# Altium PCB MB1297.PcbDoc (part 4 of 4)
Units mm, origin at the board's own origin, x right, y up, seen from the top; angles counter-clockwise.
Board outline 90.1 x 62.11 mm, 4 copper layers (Top Layer, GND, POWER+GND, Bottom Layer), stack 0.778 mm thick; 235 components, 175 nets, 1727 pads, 1 vias.
Unrouted connection lines stored in the file: 1.
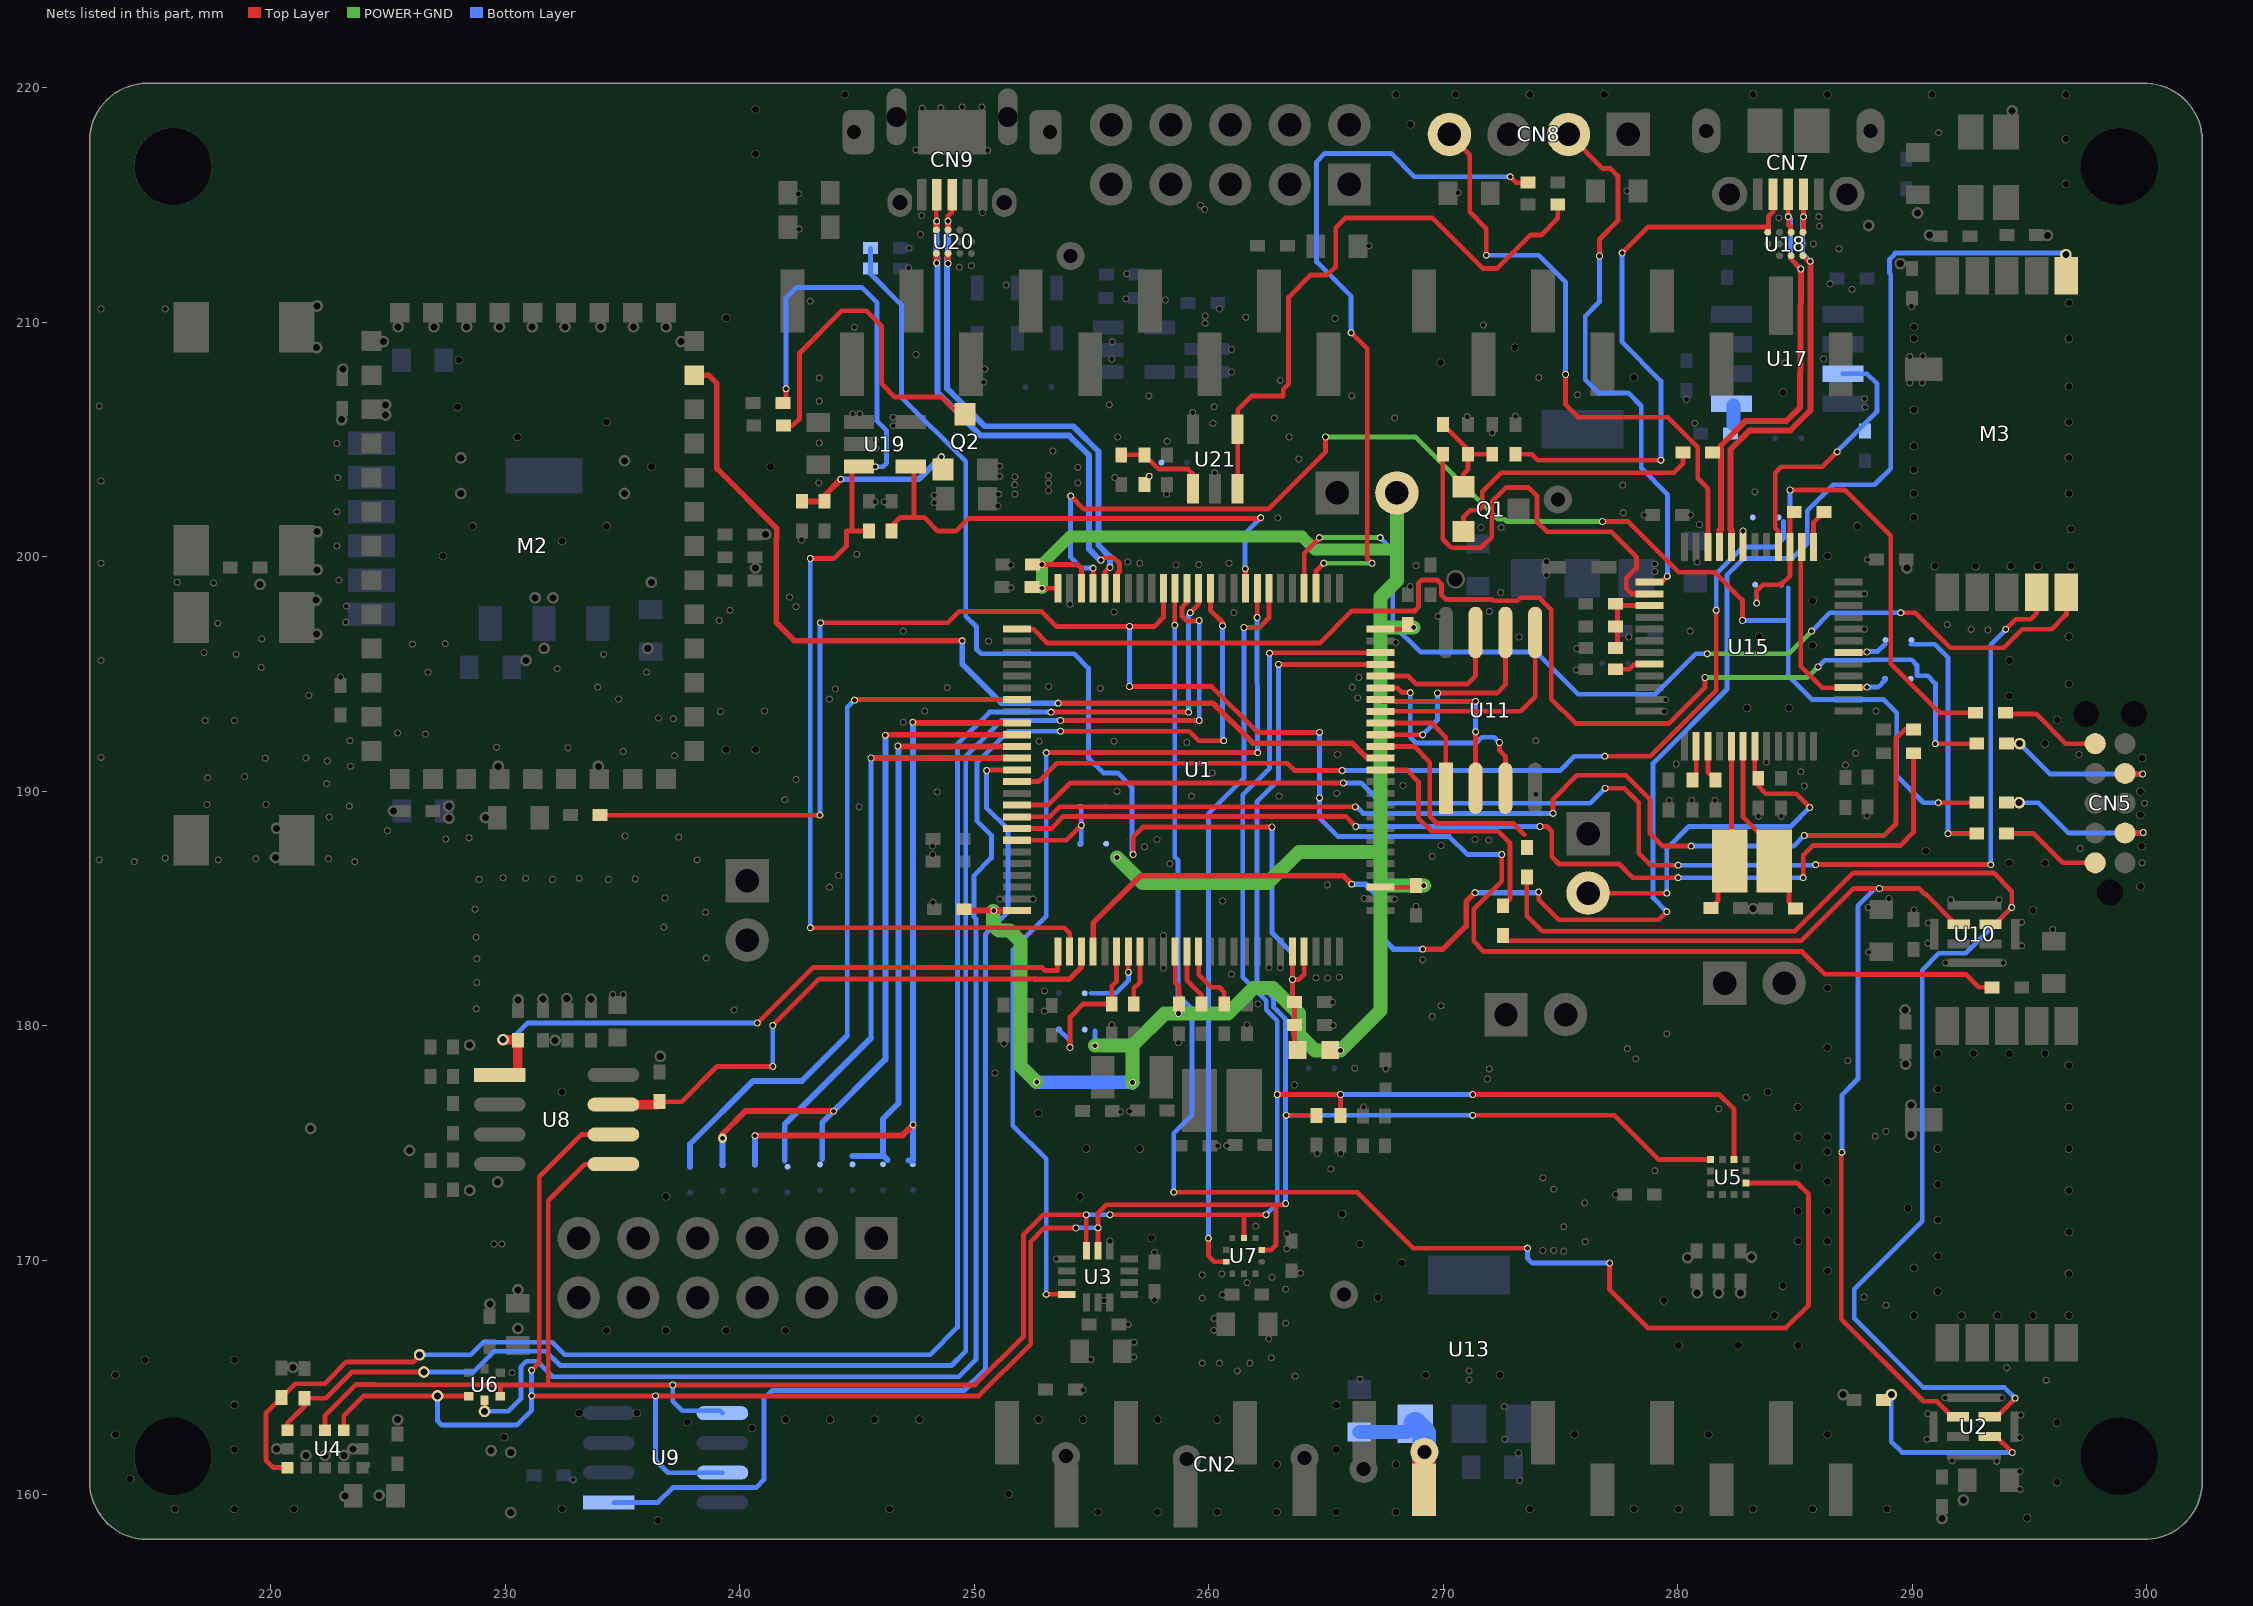
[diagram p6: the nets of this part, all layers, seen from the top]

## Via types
v1: diameter 0.4, hole 0.2, Top Layer to Bottom Layer, tented both sides, 1 vias

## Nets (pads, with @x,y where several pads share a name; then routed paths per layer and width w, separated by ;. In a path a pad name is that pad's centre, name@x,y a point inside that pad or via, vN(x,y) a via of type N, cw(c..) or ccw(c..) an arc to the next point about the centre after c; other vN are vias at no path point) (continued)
NetM2_34: M2.34 pad.33@249.479,196.418 pad.93@253.568,193.751 U1.39 | length 41.1
  Top Layer w0.24: M2.34@238.045,207.742 238.663,207.742 239.014,207.391 239.014,203.759 241.569,201.204 241.569,200.757 241.554,200.742 241.554,197.18 242.316,196.418 pad.33@249.479,196.418 ; pad.93@253.568,193.751 260.172,193.751 261.874,192.049 266.106,192.049 266.749,191.406 U1.39@267.313,191.406
  Bottom Layer w0.24: pad.33@249.479,196.418 249.479,195.422 251.15,193.751 pad.93@253.568,193.751
NetM3_1: M3.1 pad.46@279.527,184.861 pad.47@271.348,185.674 pad.49@274.066,185.699 pad.86@266.09,186.03 pad.91@269.113,183.261 pad.108@296.545,212.877 U1.4 | length 73.4
  Top Layer w0.204: pad.49@274.066,185.699 274.066,185.369 274.916,184.52 279.185,184.52 pad.46@279.527,184.861
  Top Layer w0.24: U1.4@255.063,183.156 255.063,184.374 257.073,186.385 265.735,186.385 pad.86@266.09,186.03 ; pad.91@269.113,183.261 269.977,183.261 270.967,184.252 270.967,185.293 pad.47@271.348,185.674
  Bottom Layer w0.204: pad.46@279.527,184.861 278.943,185.445 278.943,191.186 282.093,194.336 282.093,199.213 282.804,199.923 284.886,199.923 285.521,200.558 285.521,201.955 286.633,203.067 288.385,203.067 289.077,203.759 289.077,212.039 289.03,212.086 289.03,212.684 289.252,212.907 289.252,212.95 296.472,212.95 pad.108@296.545,212.877
  Bottom Layer w0.24: pad.86@266.09,186.03 266.689,186.03 267.185,185.534 267.185,183.944 267.868,183.261 pad.91@269.113,183.261 ; pad.47@271.348,185.674 274.041,185.674 pad.49@274.066,185.699
NetM3_10: M3.10 pad.23@293.98,196.901 pad.28@276.901,190.121 pad.29@280.01,186.842 pad.31@293.345,186.868 pad.32@285.877,186.868 pad.135@265.735,190.348 U1.91 | length 57.9
  Top Layer w0.204: U1.91@251.813,189.406 253.135,189.406 254.076,190.348 pad.135@265.735,190.348 ; pad.28@276.901,190.121 277.722,190.121 278.333,189.509 278.333,187.35 278.841,186.842 pad.29@280.01,186.842 ; pad.32@285.877,186.868 pad.31@293.345,186.868 ; pad.23@293.98,196.901 294.411,197.333 295.046,197.333 295.3,197.587 M3.10@295.3,198.488
  Bottom Layer w0.204: pad.135@265.735,190.348 266.497,190.348 267.36,189.484 276.265,189.484 pad.28@276.901,190.121 ; pad.29@280.01,186.842 pad.32@285.852,186.842 ; pad.31@293.345,186.868 293.345,196.24 293.98,196.875 pad.23@293.98,196.901
NetM3_11: M3.11 pad.50@264.719,200.812 pad.244 pad.245 pad.246 pad.247 U1.54 | length 42.5
  Top Layer w0.204: U1.54@264.063,198.656 264.063,200.156 pad.50@264.719,200.812 ; pad.245@289.509,197.612 290.119,197.612 291.617,196.113 293.903,196.113 294.691,196.901 295.935,196.901 296.57,197.536 M3.11@296.57,198.488
  POWER+GND w0.204: pad.50@264.719,200.812 pad.244@267.31,200.812 ; pad.247@281.254,195.859 284.734,195.859 pad.246@285.699,196.825
  Bottom Layer w0.204: pad.244@267.31,200.812 267.843,200.279 267.843,197.104 269.011,195.936 273.939,195.936 275.742,194.132 279.044,194.132 280.772,195.859 pad.247@281.254,195.859 ; pad.246@285.699,196.825 286.487,197.612 pad.245@289.509,197.612
NetQ1_1: Q1.1 R45.2 R46.2 R48.2 | length 4.2
  Top Layer w0.204: R45.2@269.977,205.638 271.043,204.572 R46.2@271.043,204.368 ; Q1.1@270.852,202.982 270.852,203.517 271.043,203.708 R46.2@271.043,204.368 ; R48.2@272.085,204.368 R46.2@271.043,204.368
NetQ1_2: Q1.2 R50.1 | length 11.8
  Top Layer w0.204: Q1.2@270.852,201.082 270.852,201.688 271.145,201.981 271.501,201.981 271.653,202.133 271.653,202.768 272.466,203.581 279.832,203.581 280.213,203.962 R50.1@280.213,204.445
NetQ2_1: pad.145@244.297,203.302 pad.146@248.59,204.267 Q2.1 R57.2 R59.2 | length 6.9
  Top Layer w0.254: R59.2@242.646,202.362 R57.2@243.606,202.362 243.606,202.611 pad.145@244.297,203.302
  Bottom Layer w0.254: pad.145@244.297,203.302 247.625,203.302 pad.146@248.59,204.267
NetQ2_3: Q2.3 R55.1 | length 14.7
  Top Layer w0.204: R55.1@241.859,205.588 242.24,205.588 242.545,205.892 242.545,208.686 244.348,210.49 245.389,210.49 246.05,209.829 246.05,207.366 246.609,206.807 248.615,206.807 249.352,206.07 Q2.3@249.606,206.07
NetR1_2: pad.32@229.895,179.4 pad.58@240.741,180.111 R1.2 U1.1 U8.1 | length 28.7
  Top Layer w0.204: pad.58@240.741,180.111 243.103,182.474 252.882,182.474 253.009,182.347 253.543,182.347 253.543,183.137 U1.1@253.563,183.156
  Top Layer w0.4: U8.1@229.756,177.902 230.556,177.902 230.53,177.927 R1.2@230.53,179.375 230.505,179.4 pad.32@229.895,179.4
  Bottom Layer w0.204: 230.226,179.4 230.937,180.111 pad.58@240.741,180.111
  Bottom Layer w0.24: pad.32@229.895,179.4 230.226,179.4
NetR4_2: pad.59@241.402,180.01 pad.60@241.402,178.257 R4.2 U1.3 U8.7 | length 24.1
  Top Layer w0.204: R4.2@236.576,176.759 237.515,176.759 239.014,178.257 pad.60@241.402,178.257 ; pad.59@241.402,180.01 243.383,181.991 252.576,181.991
  Top Layer w0.24: 252.576,181.991 252.594,181.974 254.033,181.974 254.563,182.503 U1.3@254.563,183.156
  Top Layer w0.4: U8.7@234.606,176.632 236.449,176.632 R4.2@236.576,176.759
  Bottom Layer w0.204: pad.60@241.402,178.257 pad.59@241.402,180.01
NetR5_1: R5.1 U1.12 | length 2.5
  Top Layer w0.204: U1.12@259.063,183.156 259.063,181.932 259.69,181.305 R5.1@259.69,180.924
NetR6_1: pad.165 pad.166 R6.1 U2.3 U10.3 | length 56.5
  Top Layer w0.2: R6.1@273.558,186.334 273.558,184.683 274.218,184.023 284.988,184.023 287.477,186.512 293.472,186.512 294.157,185.826 294.157,185.801 294.234,185.725 pad.166@294.234,185.039 293.526,184.331 U10.3@293.334,184.331 ; U2.3@293.3,163.327 293.604,163.327 pad.165@294.386,164.109
  Bottom Layer w0.2: pad.166@294.234,185.039 292.278,183.083 291.135,183.083 290.424,182.372 290.424,171.653 287.528,168.758 287.528,167.513 290.474,164.567 293.929,164.567 pad.165@294.386,164.109
NetR6_2: R6.2 U1.40 | length 9.1
  Top Layer w0.204: U1.40@267.313,191.906 268.748,191.906 269.418,191.237 269.418,188.925 269.723,188.62 272.974,188.62 273.456,188.138
NetR7_1: R7.1 U1.13 | length 2.9
  Top Layer w0.204: U1.13@259.563,183.156 259.563,182.169 260.096,181.635 260.452,181.635 260.655,181.432 R7.1@260.655,180.924
NetR10_2: pad.3@236.398,164.211 pad.9@262.966,195.406 pad.11@263.271,172.415 pad.14@227.101,164.211 pad.15@231.115,164.211 pad.16@231.115,165.303 pad.17@255.27,171.378 pad.18@254.33,171.374 pad.20@263.296,176.174 pad.151 R10.2 U1.47 U3.13 U4.10 U5.1 U6.2 U7.2 U8.6 U9.7 | length 121.5
  Top Layer w0.204: U4.10@223.101,162.75 223.101,163.36 223.952,164.211 pad.14@227.101,164.211 228.416,164.211 U6.2@228.433,164.194 ; pad.15@231.115,164.211 pad.3@236.398,164.211 250.19,164.211 252.401,166.422 252.401,170.791 252.984,171.374 pad.18@254.33,171.374 ; pad.16@231.115,165.303 231.445,165.633 231.445,173.558 233.248,175.362 U8.6@234.606,175.362 ; U3.13@255.27,170.391 pad.17@255.27,171.378 255.27,172.009 255.626,172.364 262.763,172.364 ; U7.2@262.256,170.43 262.632,170.43 262.865,170.663 262.865,172.364 pad.11@263.22,172.364 ; pad.9@262.966,195.406 U1.47@267.313,195.406 ; pad.20@263.296,176.174 R10.2@264.592,176.174 ; pad.151@271.247,176.174 277.292,176.174 279.171,174.295 U5.1@281.397,174.295
  Bottom Layer w0.204: pad.14@227.101,164.211 227.101,163.144 227.279,162.966 230.48,162.966 231.115,163.601 pad.15@231.115,164.211 pad.16@231.115,165.303 ; pad.3@236.398,164.211 236.398,161.468 236.931,160.934 U9.7@239.255,160.934 ; pad.18@254.334,171.378 pad.17@255.27,171.378 ; pad.9@262.966,195.406 262.966,190.475 262.052,189.56 262.052,181.896 262.75,181.198 262.75,180.808 263.22,180.338 263.22,180.309 263.268,180.261 pad.11@263.268,172.418 ; pad.20@263.395,176.174 pad.151@271.247,176.174
NetR11_2: pad.2@237.134,164.677 pad.8@262.585,195.885 pad.12@262.433,171.933 pad.13@255.778,171.933 pad.14@254.77,171.933 pad.19@262.914,177.063 pad.152@271.247,177.063 pad.153@265.608,177.063 R11.2 U1.48 U3.14 U4.9 U5.11 U6.4 U7.4 U8.5 U9.5 | length 117
  Top Layer w0.204: U4.9@222.301,162.75 222.301,163.373 223.622,164.694 224.409,164.694 224.415,164.688 229.794,164.688 229.783,164.677 ; U6.4@229.783,164.194 229.783,164.677 ; U8.5@234.606,174.092 233.375,174.092 231.826,172.542 231.826,164.677 ; U3.14@254.77,170.391 pad.14@254.77,171.933 252.933,171.933 252.095,171.094 252.095,166.751 250.021,164.677 pad.2@237.134,164.677 231.826,164.677 ; pad.13@255.778,171.933 261.493,171.933 ; U7.4@261.493,170.943 261.493,171.933 ; pad.12@262.433,171.933 261.493,171.933 ; pad.8@262.585,195.885 262.607,195.906 U1.48@267.313,195.906 ; pad.19@262.914,177.063 pad.153@265.608,177.063 R11.2@265.608,176.174 ; pad.152@271.247,177.063 281.762,177.063 282.397,176.428 U5.11@282.397,174.295 ; 229.783,164.677 231.826,164.677
  Bottom Layer w0.204: pad.2@237.134,164.677 237.134,163.975 237.535,163.574 239.155,163.574 U9.5@239.255,163.474 ; pad.14@254.77,171.933 pad.13@255.778,171.933 ; pad.12@262.433,171.933 262.914,172.414 262.914,180.212 262.444,180.682 262.444,181.071 261.442,182.073 261.442,189.84 262.585,190.983 pad.8@262.585,195.885 ; pad.153@265.608,177.063 pad.152@271.247,177.063
NetR12_1: R12.1 U1.8 | length 2.3
  Top Layer w0.204: R12.1@256.794,180.924 256.794,181.585 257.063,181.853 U1.8@257.063,183.156
NetR13_1: pad.167 pad.168 R13.1 U2.4 U10.4 | length 46.9
  Top Layer w0.2: 290.271,185.852 290.525,185.598 290.582,185.598 291.848,184.331 U10.4@291.984,184.331
  Top Layer w0.204: R13.1@272.542,183.845 272.771,183.617 285.267,183.617 287.503,185.852 pad.168@288.595,185.852 290.271,185.852 ; pad.167@286.995,174.6 286.969,174.574 286.969,167.488 290.474,163.982 291.041,163.982 291.696,163.327 U2.4@291.95,163.327
  Bottom Layer w0.204: pad.167@286.995,174.6 286.995,177.038 287.68,177.724 287.68,185.108 288.424,185.852 pad.168@288.595,185.852
NetR13_2: R13.2 U1.38 | length 10.5
  Top Layer w0.204: U1.38@267.313,190.906 268.427,190.906 268.935,190.398 268.935,188.849 269.494,188.29 272.339,188.29 272.845,187.784 272.845,185.418 R13.2@272.542,185.115
NetR14_2: pad.17@226.517,165.227 pad.25@259.588,197.282 pad.28@253.67,193.015 pad.29@259.588,193.015 R14.2 U1.64 U4.7 | length 73.5
  Top Layer w0.204: U4.7@220.701,162.75 220.701,163.043 221.437,163.779 R14.2@221.437,164.109 222.326,164.109 223.444,165.227 pad.17@226.517,165.227 ; pad.28@253.67,193.015 pad.29@259.588,193.015 ; U1.64@259.063,198.656 259.063,198.052 258.853,197.842 258.853,197.465 259.06,197.258 259.564,197.258 pad.25@259.588,197.282
  Bottom Layer w0.204: pad.17@226.517,165.227 228.625,165.227 229.514,166.116 231.724,166.116 232.334,165.506 249.022,165.506 249.633,166.118 249.633,191.492 251.155,193.015 pad.28@253.67,193.015 ; pad.29@259.588,193.015 pad.25@259.588,197.282
NetR15_2: pad.18@226.339,165.964 pad.26@259.207,197.612 pad.27@253.263,193.37 pad.30@259.131,193.37 R15.2 U1.63 U4.5 | length 75.3
  Top Layer w0.204: U4.5@220.701,161.15 220.104,161.15 219.786,161.468 219.786,163.474 R15.2@220.447,164.135 221.043,164.732 222.288,164.732 223.215,165.659 226.085,165.659 pad.18@226.339,165.964 ; pad.27@253.263,193.37 pad.30@259.131,193.37 ; pad.26@259.207,197.612 259.563,197.968 U1.63@259.563,198.656
  Bottom Layer w0.204: pad.18@226.339,165.964 228.511,165.964 229.044,166.497 232.004,166.497 232.537,165.964 248.107,165.964 249.276,167.132 249.276,191.999 250.647,193.37 pad.27@253.263,193.37 ; pad.30@259.131,193.37 259.131,197.536 pad.26@259.207,197.612
NetR16_1: pad.172 R16.1 SB1.2
NetR16_2: R16.2 R38.2 U21.1 | length 4
  Top Layer w0.204: R38.2@256.261,204.343 R16.2@257.251,204.343 257.861,203.733 259.105,203.733 259.321,203.517 U21.1@259.321,202.895
NetR18_1: R18.1 U21.3 U21.4 | length 26.1
  Top Layer w0.204: U21.3@261.226,202.895 U21.4@261.226,205.435 261.226,206.261 261.823,206.858 263.169,206.858 263.169,207.148 263.395,207.373 263.395,211.071 264.338,212.014 265.049,212.014 265.405,212.369 265.405,214.02 265.829,214.445 269.53,214.445 271.682,212.293 272.288,212.293 273.71,213.716 274.168,213.716 274.879,214.427 R18.1@274.879,215.011
NetR20_1: pad.51@264.897,199.72 pad.76@266.954,199.72 pad.77@272.847,216.205 pad.81@266.065,209.55 R20.1 U1.53 | length 31
  Top Layer w0.204: U1.53@264.563,198.656 264.563,199.386 pad.51@264.897,199.72 ; pad.81@266.065,209.55 266.751,208.864 266.751,199.923 pad.76@266.954,199.72 ; pad.77@272.847,216.205 273.101,215.951 R20.1@273.609,215.951
  POWER+GND w0.204: pad.51@264.897,199.72 pad.76@266.954,199.72
  Bottom Layer w0.204: pad.81@266.065,209.55 266.065,211.099 264.592,212.573 264.592,216.84 264.947,217.195 267.767,217.195 268.757,216.205 pad.77@272.847,216.205
NetR21_1: pad.53@272.491,187.3 pad.106@243.408,188.976 pad.107@243.434,197.18 pad.184 pad.186 pad.187 pad.193 R21.1 R22.1 U1.66 | length 84
  Top Layer w0.204: R21.1@234.036,188.976 pad.106@243.408,188.976 ; pad.107@243.434,197.18 248.868,197.18 249.352,197.664 252.857,197.664 253.493,197.028 pad.184@256.616,197.028 257.683,197.028 258.063,197.407 258.063,197.968 ; pad.193@256.616,194.462 260.121,194.462 262.077,192.507 pad.187@264.719,192.507 ; pad.53@272.491,187.3 272.491,186.157 271.297,184.963 271.297,183.591 271.729,183.159 285.293,183.159 286.258,182.194 287.604,182.194 287.619,182.179 292.293,182.179 292.837,181.635 R22.1@293.395,181.635
  Bottom Layer w0.204: pad.106@243.408,188.976 pad.107@243.408,197.155 ; pad.193@256.616,194.462 pad.184@256.616,197.028 ; pad.187@264.719,192.507 pad.186@264.719,189.713 264.719,188.849 265.506,188.062 270.256,188.062 271.018,187.3 pad.53@272.491,187.3
NetR29_1: R29.1 U15.44 | length 1.5
  Top Layer w0.204: R29.1@277.343,195.199 277.927,195.199 278.142,195.414 U15.44@278.782,195.414
NetR31_1: R31.1 U15.2 | length 1.3
  Top Layer w0.204: R31.1@280.782,190.663 U15.2@280.782,191.914
NetR32_2: pad.75@290.982,192.024 pad.239 pad.241 R32.2 SB6.1 U1.76 | length 52.7
  Top Layer w0.204: U1.76@251.813,196.906 252.521,196.906 253.111,196.317 264.718,196.317 266.09,197.688 268.783,197.688 268.936,197.841 268.936,198.857 269.088,199.009 269.739,199.009 269.917,198.831 269.917,198.384 270.13,198.171 272.085,198.171 272.134,198.122 273.153,198.122 273.279,198.247 274.091,198.247 274.599,197.739 274.599,193.929 275.641,192.888 279.629,192.888 281.153,194.412 pad.239@281.153,194.843 ; pad.75@290.982,192.024 R32.2@292.748,192.024
  POWER+GND w0.204: pad.239@281.153,194.843 285.521,194.843 pad.241@285.979,195.301
  Bottom Layer w0.204: pad.241@285.979,195.301 286.26,195.582 288.208,195.582 288.232,195.605 289.966,195.605 290.195,195.377 290.195,194.92 290.652,194.92 290.982,194.589 pad.75@290.982,192.024
NetR33_2: pad.74@291.109,189.509 pad.99@255.063,199.513 pad.212 pad.213 pad.215 pad.216 R33.2 SB5.1 U1.72 | length 56.5
  Top Layer w0.204: pad.212@254.102,202.59 254.66,202.032 254.659,202.03 262.533,202.03 264.973,204.47 pad.213@264.973,205.105 ; U1.72@255.063,198.656 pad.99@255.063,199.513 ; pad.215@276.784,201.498 277.876,201.498 280.035,199.339 281.563,199.339 282.753,198.15 pad.216@282.753,197.282 ; pad.74@291.109,189.509 R33.2@292.748,189.509
  POWER+GND w0.204: pad.213@264.973,205.105 268.808,205.105 272.315,201.598 272.612,201.598 272.712,201.498 pad.215@276.784,201.498 pad.215@276.809,201.524
  Bottom Layer w0.204: pad.212@254.102,202.59 254.102,199.974 254.563,199.513 pad.99@255.063,199.513 ; pad.216@282.753,197.282 284.709,197.282 ; 284.709,198.679 284.709,197.282 ; pad.74@291.109,189.509 290.474,189.509 289.331,190.652 289.331,193.345 288.773,193.904 285.725,193.904 284.709,194.92 284.709,197.282
NetR34_2: pad.72@291.516,188.189 R34.2 SB8.1 | length 10.6
  Top Layer w0.204: pad.72@291.516,188.189 R34.2@292.748,188.189
  Bottom Layer w0.204: 289.933,196.266 290.957,196.266 291.516,195.707 291.516,188.443 pad.72@291.516,188.189
NetR35_2: pad.14@284.782,202.842 pad.43@276.885,191.491 pad.45@281.635,197.714 pad.136@265.684,190.881 R35.2 SB7.1 U1.89 | length 57
  Top Layer w0.204: U1.89@251.813,190.406 252.738,190.406 253.517,191.186 263.347,191.186 263.652,190.881 pad.136@265.684,190.881 ; pad.43@276.885,191.491 278.816,191.491 281.635,194.31 pad.45@281.635,197.714 ; pad.14@284.785,202.844 287.122,202.844 289.077,200.889 289.077,195.428 291.16,193.345 R35.2@292.697,193.345
  Bottom Layer w0.204: pad.136@265.684,190.881 274.98,190.881 275.59,191.491 pad.43@276.885,191.491 ; pad.45@281.635,197.714 281.635,199.267 282.782,200.414 284.133,200.414 284.505,200.787 284.505,201.498 ; 284.782,201.724 pad.14@284.782,202.842 pad.14@284.785,202.844
NetR36_1: R36.1 U15.3 | length 1.6
  Top Layer w0.204: U15.3@281.282,191.914 281.282,190.802 R36.1@281.61,190.475
NetR42_2: pad.33@274.117,188.493 pad.36@280.01,186.309 pad.37@285.344,186.309 pad.134@266.268,188.493 R42.2 U1.93 | length 44.9
  Top Layer w0.204: U1.93@251.813,188.406 253.279,188.406 253.798,188.925 265.836,188.925 pad.134@266.268,188.493 ; pad.33@274.117,188.493 274.422,188.493 274.625,188.29 274.625,187.198 274.93,186.893 277.495,186.893 278.079,186.309 pad.36@280.01,186.309 ; pad.37@285.344,186.309 285.344,187.274 285.75,187.681 289.484,187.681 290.043,188.239 R42.2@290.043,191.618
  Bottom Layer w0.204: pad.134@266.268,188.493 pad.33@274.117,188.493 ; pad.36@280.01,186.309 pad.37@285.344,186.309
NetR43_2: pad.38@285.394,188.112 pad.39@280.568,187.655 pad.40@274.676,189.052 pad.133@266.243,189.332 R43.2 U1.92 | length 45.8
  Top Layer w0.204: U1.92@251.813,188.906 253.219,188.906 253.644,189.332 pad.133@266.243,189.332 ; pad.40@274.676,189.052 274.676,189.662 275.692,190.678 277.774,190.678 278.816,189.636 278.816,188.189 279.349,187.655 pad.39@280.568,187.655 ; pad.38@285.394,188.112 288.798,188.112 289.306,188.62 289.306,192.253 289.687,192.634 R43.2@290.043,192.634
  Bottom Layer w0.204: pad.133@266.243,189.332 266.294,189.332 266.573,189.052 pad.40@274.676,189.052 ; pad.39@280.568,187.655 284.937,187.655 pad.38@285.394,188.112
NetR53_2: R53.2 U17.5 | length 0.8
  Bottom Layer w0.6: 282.372,205.664 U17.5@282.372,206.438
NetR56_1: pad.57@243.002,184.175 pad.115@243.002,199.923 pad.121@245.77,203.835 pad.144@241.96,207.162 R56.1 R58.2 U1.2 U19.3 | length 51
  Top Layer w0.204: R56.1@241.833,206.553 241.96,206.68 pad.144@241.96,207.162 ; pad.57@243.002,184.175 253.82,184.175 254.063,183.933 U1.2@254.063,183.156 ; pad.115@243.002,199.923 244.018,199.923 244.541,200.447 244.541,201.092 R58.2@245.501,201.092 244.831,201.092 244.78,201.143 244.78,203.553 U19.3@245.077,203.85
  Bottom Layer w0.204: pad.144@241.96,207.162 241.96,211.023 242.418,211.48 245.186,211.48 245.847,210.82 245.847,205.773 246.253,205.366 246.253,203.987 246.101,203.835 pad.121@245.77,203.835 ; pad.57@243.002,184.175 pad.115@243.002,199.923
NetR62_2: pad.131@262.204,201.663 pad.132@261.553,199.482 R62.2 U1.59 U19.4 | length 22.1
  Top Layer w0.204: R62.2@246.461,201.092 246.461,201.3 246.837,201.676 247.371,201.676 ; U19.4@247.277,203.85 247.422,203.705 247.422,201.727 247.371,201.676 ; pad.132@261.544,199.492 261.563,199.473 U1.59@261.563,198.656 ; pad.131@262.204,201.676 262.153,201.625 249.741,201.625 249.208,201.092 248.437,201.092 247.853,201.676 247.371,201.676
  Bottom Layer w0.204: pad.132@261.544,199.492 261.544,200.99 262.204,201.651 pad.131@262.204,201.676
NetR67_2: pad.45@289.103,164.262 pad.94@294.259,161.798 R67.2 U2.2 | length 8.6
  Top Layer w0.204: U2.2@293.3,162.477 293.58,162.477 pad.94@294.259,161.798
  Bottom Layer w0.204: pad.45@289.103,164.262 289.103,162.255 289.56,161.798 pad.94@294.259,161.798
NetSB3_1: pad.48@256.565,182.27 SB3.1 U1.7 | length 3.1
  Top Layer w0.204: U1.7@256.563,183.156 256.563,182.273 pad.48@256.565,182.27
  Bottom Layer w0.204: 254.965,181.381 256.032,181.381 256.565,181.915 pad.48@256.565,182.27
NetSB9_2: pad.54@254.559,188.544 SB9.2 SB13.2 U1.94 | length 4.6
  Top Layer w0.204: U1.94@251.813,187.906 253.921,187.906 pad.54@254.559,188.544
  Bottom Layer w0.204: SB9.2@254.518,187.757 254.559,187.798 pad.54@254.559,188.544 254.559,189.29 SB13.2@254.518,189.332
NetSB12_2: pad.132@246.736,191.922 SB12.2 SB14.2 U1.86 | length 24.4
  Top Layer w0.254: pad.132@246.752,191.906 U1.86@251.813,191.906
  Bottom Layer w0.254: 244.802,174.432 246.141,174.432 246.304,174.269 ; 246.101,174.438 246.101,176.028 246.761,176.688 246.761,191.897 pad.132@246.736,191.922
NetSB15_2: pad.2@243.992,176.352 pad.131@246.202,192.38 SB15.2 SB16.2 U1.85 | length 31.2
  Top Layer w0.254: v1(239.257,175.198) 239.257,175.376 240.233,176.352 pad.2@243.992,176.352 ; pad.131@246.202,192.38 246.28,192.406 U1.85@251.813,192.406
  Bottom Layer w0.254: SB16.2@239.257,174.057 v1(239.257,175.198) ; 243.51,174.32 243.51,175.87 246.202,178.562 pad.131@246.202,192.38
NetSB18_2: pad.0@240.643,175.307 pad.1@247.384,175.768 pad.130@247.371,192.938 SB18.2 SB19.2 U1.84 | length 31.5
  Top Layer w0.254: pad.0@240.643,175.307 246.923,175.307 pad.1@247.384,175.768 ; pad.130@247.371,192.938 247.466,192.906 U1.84@251.813,192.906
  Bottom Layer w0.254: SB18.2@240.643,174.082 pad.0@240.643,175.307 ; 247.182,174.254 247.385,174.254 pad.1@247.384,175.768 pad.130@247.371,192.938
NetSB20_1: pad.133@245.593,191.414 SB20.1 U1.87 | length 24.9
  Top Layer w0.254: pad.133@245.593,191.414 245.661,191.406 U1.87@251.813,191.406
  Bottom Layer w0.204: 245.593,179.476 pad.133@245.593,191.414
  Bottom Layer w0.254: 241.91,174.244 241.91,175.793 245.593,179.476
NetSB21_1: pad.134@244.881,193.878 SB21.1 U1.82 | length 31
  Top Layer w0.204: pad.134@244.91,193.906 U1.82@251.813,193.906
  Top Layer w0.254: pad.134@244.881,193.878 pad.134@244.91,193.906
  Bottom Layer w0.204: 244.577,179.578 244.577,193.573 pad.134@244.881,193.878
  Bottom Layer w0.254: SB21.1@237.871,173.982 237.871,174.955 240.563,177.648 242.646,177.648 244.577,179.578
NetU1_41: pad.58@269.748,194.183 pad.59@269.113,192.405 U1.41 U11.6 | length 8.2
  Top Layer w0.204: U1.41@267.313,192.406 269.112,192.406 pad.59@269.113,192.405 ; pad.58@269.748,194.183 272.288,194.183 272.644,194.539 U11.6@272.644,195.871
  Bottom Layer w0.204: pad.59@269.113,192.405 269.748,193.04 pad.58@269.748,194.183
NetU1_42: U1.42 U11.1 | length 4.3
  Top Layer w0.204: U1.42@267.313,192.906 269.501,192.906 270.104,192.303 U11.1@270.104,191.021
NetU1_43: U1.43 U11.5 | length 8.7
  Top Layer w0.204: U1.43@267.313,193.406 273.289,193.406 273.914,194.031 U11.5@273.914,195.871
NetU1_44: pad.62@271.374,192.532 pad.63@271.372,193.829 U1.44 U11.2 | length 9.2
  Top Layer w0.204: U1.44@267.313,193.906 267.39,193.829 pad.63@271.372,193.829 ; U11.2@271.374,190.627 pad.62@271.374,192.532 ; U11.2@271.374,191.021 271.374,191.124 271.456,191.124 271.572,191.008 U11.2@271.572,189.459
  Bottom Layer w0.204: pad.63@271.372,193.829 271.372,192.534 pad.62@271.374,192.532
NetU1_45: pad.60@268.586,194.202 pad.61@272.39,192.075 U1.45 U11.3 | length 9.1
  Top Layer w0.204: U1.45@267.313,194.406 268.038,194.406 268.243,194.202 pad.60@268.586,194.202 ; pad.61@272.39,192.075 272.39,191.745 272.644,191.491 U11.3@272.644,190.449
  Bottom Layer w0.204: pad.60@268.586,194.202 268.586,192.297 268.832,192.051 271.393,192.051 271.639,192.297 272.168,192.297 pad.61@272.39,192.075
NetU1_46: U1.46 U11.7 | length 5.3
  Top Layer w0.204: U1.46@267.313,194.906 268.503,194.906 268.845,194.564 271.018,194.564 271.374,194.92 U11.7@271.374,195.871
NetU1_57: pad.39@259.977,170.934 pad.40@261.493,196.977 U1.57 U7.7 | length 30.8
  Top Layer w0.204: pad.39@259.977,170.934 259.977,170.18 260.227,169.93 U7.7@260.73,169.93 ; pad.40@261.493,196.977 262.153,196.977 262.563,197.386 U1.57@262.563,198.656
  Bottom Layer w0.204: pad.39@259.977,170.934 259.977,189.036 261.493,190.552 pad.40@261.493,196.977
NetU1_58: pad.23@253.06,168.541 pad.24@262.056,197.409 pad.31@262.077,191.643 pad.32@253.06,191.643 U1.58 U3.4 | length 41.1
  Top Layer w0.204: pad.23@253.06,168.541 U3.4@253.94,168.541 ; pad.32@253.06,191.643 pad.31@262.077,191.643 ; pad.24@262.056,197.409 262.063,197.674 U1.58@262.063,198.656
  Bottom Layer w0.204: pad.23@253.06,168.541 253.06,174.316 251.638,175.739 251.638,183.236 253.06,184.658 pad.32@253.06,191.643 ; pad.24@262.056,197.409 pad.31@262.077,191.694
NetU1_62: pad.15@229.108,163.551 pad.35@253.67,192.557 pad.36@260.579,197.053 pad.37@260.629,192.151 U1.62 U6.3 | length 67.7
  Top Layer w0.204: pad.15@229.108,163.551 U6.3@229.108,164.019 ; pad.35@253.67,192.557 259.156,192.557 259.563,192.151 pad.37@260.629,192.151 ; U1.62@260.063,198.656 260.063,197.722 260.579,197.206 pad.36@260.579,197.053
  Bottom Layer w0.204: pad.15@229.108,163.551 230.124,163.551 230.657,164.084 230.657,165.454 230.886,165.683 231.351,165.683 232.01,165.024 236.981,165.024 236.988,165.031 237.281,165.031 237.288,165.024 249.326,165.024 250.063,165.76 250.063,184.563 249.987,184.639 249.987,186.418 250.723,187.155 250.723,188.112 250.114,188.722 250.114,191.237 251.435,192.557 pad.35@253.67,192.557 ; pad.37@260.579,192.202 pad.36@260.579,197.053
NetU1_65: pad.155@258.547,197.079 pad.156@258.496,172.898 pad.157 pad.159 U1.65 U5.8 | length 64.8
  Top Layer w0.204: pad.156@258.496,172.898 266.319,172.898 268.707,170.51 pad.157@273.583,170.51 ; pad.155@258.547,197.079 258.547,198.641 U1.65@258.563,198.656 ; pad.159@277.089,169.875 277.089,168.732 278.714,167.107 284.607,167.107 285.572,168.072 285.572,172.803 285.08,173.295 U5.8@282.897,173.295
  Bottom Layer w0.204: pad.156@258.496,172.898 258.496,175.412 259.283,176.2 259.283,180.696 258.684,181.295 258.684,187.053 258.547,187.191 pad.155@258.547,197.079 ; pad.157@273.583,170.51 273.583,170.078 273.787,169.875 pad.159@277.089,169.875
NetU1_88: pad.156@250.52,190.881 U1.88 U9.1 | length 47.8
  Top Layer w0.204: pad.156@250.52,190.881 250.546,190.906 U1.88@251.813,190.906
  Bottom Layer w0.204: U9.1@234.62,159.664 236.499,159.664 237.134,160.299 240.69,160.299 241.021,160.63 241.021,164.084 241.376,164.44 249.555,164.44 250.469,165.354 250.469,183.898 251.433,184.861 251.433,188.368 250.52,189.281 pad.156@250.52,190.881
OSC_IN: C52.2 U15.5 X3.2 | length 7.3
  Top Layer w0.204: C52.2@281.407,185.014 281.711,185.318 281.711,186.522 X3.2@282.209,187.02 282.282,187.093 U15.5@282.282,191.914
OSC_OUT: C51.2 U15.6 X3.1 | length 7.9
  Top Layer w0.204: U15.6@282.782,191.914 282.782,188.896 284.109,187.569 X3.1@284.109,187.02 284.734,186.395 284.734,185.267 C51.2@285.013,184.988
PWR_ENN: pad.20@286.791,204.47 R51.1 U15.28 U17.3 | length 11.5
  Top Layer w0.204: U15.28@284.282,200.414 284.282,201.088 284.15,201.22 284.15,203.581 284.404,203.835 286.156,203.835 pad.20@286.791,204.47
  Bottom Layer w0.204: pad.20@286.779,204.483 288.493,206.197 288.493,207.366 288.061,207.797 U17.3@287.033,207.797
PWR_EXT: R27.1 R28.2 R30.2 U15.39 | length 3.2
  Top Layer w0.204: R27.1@277.343,196.113 277.421,196.192 277.421,197.914 U15.39@278.782,197.914
STM_JTCK: CN8.2 pad.70@276.657,212.827 pad.71@279.552,199.164 U15.37 | length 23.6
  Top Layer w0.204: CN8.2@275.336,218.008 276.784,216.56 277.114,216.56 277.444,216.23 277.444,214.325 276.657,213.538 pad.70@276.657,212.827 ; U15.37@278.782,198.914 279.302,198.914 pad.71@279.552,199.164
  Bottom Layer w0.204: pad.70@276.657,212.827 276.657,210.871 276.047,210.261 276.047,207.543 276.606,206.985 277.876,206.985 278.435,206.426 278.435,203.784 279.552,202.667 pad.71@279.552,199.164
STM_JTMS: CN8.4 pad.68@275.209,207.772 pad.69@271.831,212.852 U15.34 | length 25.7
  Top Layer w0.204: CN8.4@270.256,218.008 271.12,217.145 271.12,214.706 271.831,213.995 pad.69@271.831,212.852 ; pad.68@275.209,207.772 275.209,206.477 275.742,205.943 279.574,205.943 280.848,204.67 280.848,203.352 281.282,202.918 U15.34@281.282,200.414
  Bottom Layer w0.204: pad.69@271.831,212.852 274.066,212.852 275.209,211.709 pad.68@275.209,207.772
STM_RST: C54.1 JP8.2 pad.34@279.527,185.649 pad.35@285.623,189.306 U15.7 | length 16.4
  Top Layer w0.204: JP8.2@276.174,185.649 pad.34@279.527,185.649 ; U15.7@283.282,191.914 283.282,190.695 C54.1@283.426,190.551 283.426,190.221 283.756,189.89 285.039,189.89 pad.35@285.623,189.306
  Bottom Layer w0.204: pad.34@279.527,185.649 279.527,187.554 280.467,188.493 284.81,188.493 pad.35@285.623,189.306
T_JTCK: pad.71@288.061,194.437 SB6.2 U15.15 U15.26 | length 9.3
  Top Layer w0.204: U15.26@285.282,200.414 285.242,200.374 285.242,195.326 286.154,194.414 U15.15@287.282,194.414 288.039,194.414 pad.71@288.061,194.437
  Bottom Layer w0.204: pad.71@288.061,194.437 288.544,194.437 288.833,194.726 SB6.2@288.833,194.793
T_JTMS: pad.50@283.362,198.018 R39.2 SB5.2 U15.27 | length 5.5
  Top Layer w0.204: pad.50@283.362,198.018 283.362,198.552 283.616,198.806 284.396,198.806 284.782,199.192 U15.27@284.782,200.414 284.782,201.724 R39.2@284.963,201.905
  Bottom Layer w0.204: pad.50@283.362,198.018 283.362,198.552
T_NRST: pad.70@288.061,195.936 SB8.2 U15.18 | length 1.7
  Top Layer w0.204: U15.18@287.282,195.914 pad.70@288.04,195.914
  Bottom Layer w0.204: pad.70@288.061,195.936 288.087,195.961 288.528,195.961 288.833,196.266
T_SWDIO_IN: R39.1 U15.25 | length 1.7
  Top Layer w0.204: U15.25@285.782,200.414 285.782,201.454 R39.1@286.233,201.905
T_SWO: pad.13@282.778,201.092 SB7.2 U15.31
TAG_NRST: CN5.10 R34.1 | length 4.3
  Top Layer w0.204: R34.1@294.018,188.189 295.173,188.189 296.418,186.944 297.078,186.944 CN5.10@297.798,186.944
TAG_SWCLK: CN5.4 pad.0@299.822,190.729 pad.50@294.577,192.024 R32.1 | length 7.1
  Top Layer w0.204: R32.1@294.018,192.024 pad.50@294.577,192.024 ; CN5.4@299.068,190.754 299.093,190.729 pad.0@299.822,190.729
  Bottom Layer w0.204: pad.50@294.577,192.024 295.872,190.729 pad.0@299.822,190.729
TAG_SWDIO: CN5.2 pad.1@299.847,188.239 pad.51@294.551,189.509 R33.1 | length 7.2
  Top Layer w0.204: R33.1@294.018,189.509 pad.51@294.551,189.509 ; CN5.2@299.068,188.214 299.822,188.214 pad.1@299.847,188.239
  Bottom Layer w0.204: pad.51@294.551,189.509 295.377,189.509 296.672,188.214 299.822,188.214 pad.1@299.847,188.239
TAG_SWO: CN5.6 R35.1 | length 4.6
  Top Layer w0.204: R35.1@293.967,193.345 294.018,193.294 R35.1@294.094,193.294 ; R35.1@293.992,193.192 R35.1@294.094,193.294 ; R35.1@294.119,193.319 R35.1@294.094,193.294 ; CN5.6@297.798,192.024 296.545,192.024 295.275,193.294 R35.1@294.094,193.294
USB_N: CN9.2 pad.1@248.387,214.308 pad.2@248.387,212.522 pad.9@255.397,199.847 U1.70 U20.D1 U20.D3 | length 22.9
  Top Layer w0.204: pad.1@248.373,214.216 248.373,214.249 248.373,215.409 CN9.2@248.397,215.433 ; pad.9@255.397,199.847 255.5,199.95 255.947,199.95 256.186,199.711 256.186,199.373 256.079,199.267
  Top Layer w0.254: U20.D3@248.373,212.936 248.373,212.535 pad.2@248.387,212.522 ; U20.D1@248.373,213.936 pad.1@248.373,214.216
  Bottom Layer w0.254: pad.1@248.387,214.308 248.387,212.801 248.426,212.762 248.426,207.009 250.277,205.158 254.048,205.158 254.889,204.318 254.889,200.32 pad.9@255.372,199.837
USB_P: CN9.3 pad.6@248.869,214.308 pad.7@248.873,212.5 pad.10@255.778,199.542 U1.71 U20.C1 U20.C3 | length 22.9
  Top Layer w0.204: pad.6@248.873,214.216 248.873,214.253 248.873,214.532 249.047,214.706 CN9.3@249.047,215.433 ; U1.71@255.563,198.656 255.563,199.327 pad.10@255.778,199.542
  Top Layer w0.254: pad.7@248.869,212.496 pad.7@248.873,212.5 U20.C3@248.873,212.936 ; U20.C1@248.873,213.936 pad.6@248.873,214.216
  Bottom Layer w0.254: pad.6@248.869,214.308 248.869,212.776 248.83,212.736 248.83,207.176 250.444,205.562 254.216,205.562 255.293,204.485 255.293,200.487 255.776,200.004 255.776,199.544 pad.10@255.778,199.542
USB_RENUMN: R45.1 U15.38 | length 18.4
  Top Layer w0.204: R45.1@269.977,204.368 269.977,200.744 270.293,200.428 270.312,200.428 270.359,200.381 271.602,200.381 272.059,200.838 272.059,202.336 272.669,202.946 273.634,202.946 273.99,202.59 273.99,201.498 274.422,201.066 277.165,201.066 278.232,200 278.232,199.522 277.8,199.09 277.8,198.653 278.039,198.414 U15.38@278.782,198.414
USB_STLK_ID: CN7.4 pad.85@277.622,212.954 pad.86@279.274,204.11 R54.1 U18.A3 | length 24.4
  Top Layer w0.204: R54.1@273.075,204.368 273.761,204.368 274.019,204.11 pad.86@279.274,204.11 ; pad.85@277.622,212.954 278.732,214.063 283.832,214.063 U18.A3@283.832,213.835 283.87,213.873 283.87,214.528 284.059,214.717 CN7.4@284.059,215.458
  Bottom Layer w0.204: pad.85@277.622,212.954 277.622,209.144 279.274,207.491 pad.86@279.274,204.11
USB_STLK_N: CN7.2 pad.12@285.359,214.503 pad.14@285.648,212.598 U15.32 U18.D1 U18.D3 | length 18.6
  Top Layer w0.204: U18.D1@285.332,212.835 285.568,212.598 pad.14@285.648,212.598 ; U18.D3@285.359,213.944 pad.12@285.359,214.503 CN7.2@285.359,215.458
  Top Layer w0.254: U15.32@282.282,200.414 282.282,201.143 282.245,201.143 282.245,204.572 283.06,205.387 284.8,205.387 285.648,206.235 pad.14@285.648,212.598
  Bottom Layer w0.204: pad.12@285.359,214.503 285.318,214.463 285.318,212.928 pad.14@285.648,212.598
USB_STLK_P: CN7.3 pad.11@284.709,214.503 pad.13@285.241,212.268 R50.2 U15.33 U18.C1 U18.C3 | length 19.2
  Top Layer w0.204: CN7.3@284.709,215.458 pad.11@284.709,214.503 284.709,214.161 284.806,214.063 U18.C3@284.806,213.86 ; U18.C1@284.832,212.835 284.832,212.678 pad.13@285.241,212.268
  Top Layer w0.254: U15.33@281.782,200.414 281.782,201.143 281.841,201.143 281.841,204.739 282.893,205.791 284.632,205.791 285.217,206.375 pad.13@285.241,212.268
  Bottom Layer w0.204: pad.11@284.709,214.503 284.81,214.401 284.81,212.699 pad.13@285.241,212.268
VBAT: C8.2 pad.50@254.076,179.07 SB17.2 U1.6 | length 6.6
  Top Layer w0.204: pad.50@254.076,179.07 254.076,180.365 254.635,180.924 C8.2@255.854,180.924 255.854,181.686 256.063,181.895 U1.6@256.063,183.156
  Bottom Layer w0.204: SB17.2@253.603,179.832 254.076,179.359 pad.50@254.076,179.07
VDD_MCU: C7.1 C9.1 C10.1 C11.1 C12.1 C13.1 JP5.2 L1.1 pad.51@255.143,179.146 pad.52@258.699,180.518 pad.53@256.083,187.173 pad.64@269.164,185.979 pad.68@268.732,196.977 pad.95@256.743,177.571 pad.97@252.652,177.597 pad.117@265.608,178.943 pad.129@252.882,199.669 pad.130@252.882,198.656 pad.135@250.825,184.912 SB9.1 SB17.1 U1.11 U1.28 U1.50 U1.73 U1.75 U1.100 | length 96.6
  Top Layer w0.204: C12.1@252.451,198.704 252.498,198.656 pad.130@252.882,198.656 U1.75@253.563,198.656 ; C7.1@252.476,199.669 pad.129@252.882,199.669 254.406,199.669 254.563,199.513 U1.73@254.563,198.656 ; U1.11@258.563,183.156 258.563,181.823 258.724,181.661 C9.1@258.724,180.924 ; U1.28@267.313,185.906 268.761,185.906 C10.1@268.834,185.979 ; U1.50@267.313,196.906 268.28,196.906 C11.1@268.478,197.104
  Top Layer w0.254: C13.1@249.555,184.963 249.611,184.906 U1.100@251.813,184.906
  POWER+GND w0.5: pad.130@252.882,198.656 pad.129@252.882,199.669 254.076,200.863 263.982,200.863 263.982,200.839 264.511,200.31 268.074,200.31 268.017,200.254
  POWER+GND w0.6: pad.135@250.803,184.89 250.803,184.299 251.054,184.048 251.511,184.048 251.968,183.591 251.968,178.28 pad.97@252.652,177.597 ; pad.51@255.143,179.146 256.743,179.146 ; pad.53@256.083,187.173 257.175,186.08 262.509,186.08 263.835,187.406 267.313,187.406 ; pad.95@256.743,177.571 256.743,179.146 ; JP5.2@268.017,202.717 268.017,200.254 268.017,198.98 267.313,198.275 267.313,196.977 ; pad.68@268.732,196.977 267.313,196.977 ; pad.64@269.164,185.979 267.313,185.979 ; 256.743,179.146 258.115,180.518 pad.52@258.699,180.518 260.812,180.518 261.905,181.61 262.738,181.61 263.83,180.518 263.83,179.629 264.516,178.943 pad.117@265.608,178.943 267.313,180.648 267.313,185.979 ; 267.313,185.979 267.313,187.406 ; 267.313,187.406 267.313,196.977
  Bottom Layer w0.204: pad.51@255.143,179.146 255.143,179.781
  Bottom Layer w0.6: pad.97@252.652,177.597 pad.95@256.743,177.571
VDDA: C1.1 C5.1 C6.2 L1.2 pad.30@263.563,181.966 pad.31@262.687,188.468 pad.32@256.769,187.3 R2.2 U1.21 U1.22 | length 52.7
  Top Layer w0.204: pad.32@256.769,187.3 256.769,188.062 257.175,188.468 pad.31@262.687,188.468 ; U1.21@263.563,183.156 pad.30@263.563,181.966 ; L1.2@263.779,178.968 263.652,179.095 C5.1@263.652,180.035 C6.2@263.652,181 263.563,181.09 pad.30@263.563,181.966 ; U1.22@264.063,183.156 264.063,182.198 263.83,181.966 pad.30@263.563,181.966
  Bottom Layer w0.204: C1.1@245.567,213.157 R2.2@245.567,212.293 245.567,212.065 246.886,210.745 246.886,206.808 249.631,204.064 249.631,197.46 250.088,197.002 250.088,196.059 250.288,195.859 254.254,195.859 254.864,195.25 254.864,191.414 255.499,190.779 256.107,190.779 256.717,190.17 256.717,187.352 pad.32@256.769,187.3 ; pad.31@262.687,188.468 262.687,183.972 263.563,183.096 pad.30@263.563,181.966
VIN: C38.1 CN2.8 pad.48@269.189,161.823 U13.3 | length 5
  Top Layer w1: CN2.8@269.165,160.202 269.165,161.799 pad.48@269.189,161.823
  Bottom Layer w0.6: C38.1@266.421,162.674 U13.3@268.456,162.674
  Bottom Layer w1: U13.3@268.798,163.017 269.189,162.626 pad.48@269.189,161.823
pads on no net: CN5.7 CN5.8 CN5.9 CN5.11 CN5.12 CN5.13 CN9.11 CN9.12 CN10.9 CN10.10 JP4.7 M1.1 M1.2 M1.3 M2.18 M2.19 M2.23 M2.24 M2.25 M2.26 M2.27 M2.30 M2.31 M2.32 M3.2 M3.3 M3.4 U3.2 U3.3 U3.9 U3.10 U3.11 U4.8 U5.7 U9.3 U9.6 U9.8 U15.4 U15.11 U15.14 U15.16 U15.17 U15.19 U15.21 U15.22 U15.29 U15.40 U15.41 U15.42 U15.43 U15.45 U15.46 U18.A2 U18.B1 U18.B2 U18.C2 U20.A2 U20.B1 U20.B2 U20.C2

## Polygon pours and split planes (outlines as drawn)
GND on GND "Layer GND" (solid, remove dead copper, pour order 22): 210.414,210.871 239.878,210.871 239.878,221.844 297.104,221.844 297.104,198.704 297.104,194.559 297.231,194.559 299.578,194.559 299.598,194.559 cw(c299.598,193.726) 300.431,193.726 300.401,193.695 300.401,186.011 300.401,185.999 299.034,184.633 cw(c298.482,185.184) 298.482,184.404 297.155,184.404 297.129,184.404 297.129,177.825 297.129,157.074 297.053,157.074 284.785,157.074 284.785,176.251 279.502,176.251 279.502,170.917 284.785,170.917 284.785,157.124 211.049,157.124 211.049,166.37 228.6,166.37 228.6,170.942 231.267,170.942 231.267,180.365 228.498,180.365 228.498,185.826 228.498,185.852 210.795,185.852 210.464,185.852 210.464,210.795
GND on Top Layer "Top GND" (solid, remove dead copper, pour order 21): 210.43,210.882 239.894,210.882 239.894,221.855 297.12,221.855 297.12,198.715 297.12,194.57 297.247,194.57 299.595,194.57 299.615,194.57 cw(c299.615,193.737) 300.448,193.737 300.417,193.706 300.417,186.022 300.417,186.01 299.051,184.644 cw(c298.499,185.196) 298.499,184.415 297.171,184.415 297.146,184.415 297.146,177.837 297.146,157.085 297.07,157.085 284.801,157.085 284.801,176.262 279.518,176.262 279.518,170.928 284.801,170.928 284.801,157.136 211.065,157.136 211.065,166.381 228.617,166.381 228.617,170.953 231.284,170.953 231.284,180.377 228.515,180.377 228.515,185.838 228.515,185.863 210.811,185.863 210.481,185.863 210.481,210.806
GND on Bottom Layer "Layer GND" (solid, remove dead copper, pour order 20): 210.414,210.871 239.878,210.871 239.878,221.844 297.104,221.844 297.104,198.704 297.104,194.559 297.231,194.559 299.578,194.559 299.598,194.559 cw(c299.598,193.726) 300.431,193.726 300.401,193.695 300.401,186.011 300.401,185.999 299.034,184.633 cw(c298.482,185.184) 298.482,184.404 297.155,184.404 297.129,184.404 297.129,177.825 297.129,157.074 297.053,157.074 284.785,157.074 284.785,176.251 279.502,176.251 279.502,170.917 284.785,170.917 284.785,157.124 211.049,157.124 211.049,166.37 228.6,166.37 228.6,170.942 231.267,170.942 231.267,180.365 228.498,180.365 228.498,185.826 228.498,185.852 210.795,185.852 210.464,185.852 210.464,210.795
GND on POWER+GND "Power GND" (solid, remove dead copper, pour order 19): 210.414,210.896 239.878,210.896 239.878,221.869 297.104,221.869 297.104,198.73 297.104,194.584 297.231,194.584 299.578,194.584 299.598,194.584 cw(c299.598,193.751) 300.431,193.751 300.401,193.721 300.401,186.037 300.401,186.024 299.034,184.658 cw(c298.482,185.21) 298.482,184.429 297.155,184.429 297.129,184.429 297.129,177.851 297.129,157.099 297.053,157.099 284.785,157.099 284.785,176.276 279.502,176.276 279.502,170.942 284.785,170.942 284.785,157.15 211.049,157.15 211.049,166.395 228.6,166.395 228.6,170.967 231.267,170.967 231.267,180.391 228.498,180.391 228.498,185.852 228.498,185.877 210.795,185.877 210.464,185.877 210.464,210.82

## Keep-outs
Keep-Out Layer:
  lines w0.1: 212.315,217.727 cw(c214.73,217.727) 214.73,220.142 ; 212.319,217.955 212.319,160.552 ccw(c214.734,160.552) 214.734,158.137 ; 214.73,220.14 299.999,220.14 ; 214.734,158.14 300.001,158.14 ; 299.898,220.142 cw(c299.898,217.726) 302.313,217.726 ; 299.899,158.14 ccw(c299.899,160.555) 302.315,160.555 ; 302.319,160.555 302.319,217.955

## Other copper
Top Layer:
  text "1" at 213.081,211.658 h1
GND:
  text "2" at 214.581,211.658 h1
POWER+GND:
  text "3" at 216.481,211.658 h1
Bottom Layer:
  text "4" at 218.781,211.658 h1
Multi-Layer:
  pour cut-out: 212.581,213.008 212.581,211.008 219.331,211.008 219.331,213.008

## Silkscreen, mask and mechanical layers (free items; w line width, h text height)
Top Overlay:
  drawing of 620 lines, arcs and shapes, not listed
  text "USB STLINK" at 274.269,219.075 h0.8
  text "USB" at 241.478,218.77 h0.8
  text "OTG" at 241.478,217.678 h0.8
  text "D7" at 268.681,212.852 h0.7
  text "D6" at 271.17,212.852 h0.7
  text "D5" at 273.66,212.852 h0.7
  text "D15" at 241.478,212.446 h0.7
  text "D14" at 244.043,212.446 h0.7
  text "D13" at 251.663,212.446 h0.7
  text "D12" at 254.66,212.446 h0.7
  text "D11" at 256.845,212.446 h0.7
  text "D10" at 259.309,212.446 h0.7
  text "AVDD" at 246.202,206.502 h0.7
  text "D9" at 262.153,205.816 h0.7
  text "D8" at 264.592,205.816 h0.7
  text "D4" at 276.301,205.816 h0.7
  text "D3" at 278.867,205.816 h0.7
  text "D2" at 281.432,205.816 h0.7
  text "D1" at 284.277,205.816 h0.7
  text "D0" at 286.461,205.816 h0.7
  text "GND" at 252.552,205.105 h0.7
  text "USER" at 215.621,203.149 h1 r90
  text "RESET" at 215.519,190.779 h1 r90
  text "MB1297C" at 215.9,183.947 h1
  text "X" at 282.296,175.489 h0.51
  text "Z" at 284.201,175.489 h0.51
  text "Y" at 284.099,174.244 h0.51
  text "B-L475E-IOT01A1" at 238.785,174.092 h1.52
  text "Y" at 251.866,172.771 h0.51
  text "X" at 253.39,171.755 h0.51
  text "Z" at 251.638,170.764 h0.51
  text "PMOD" at 248.615,168.148 h1 r90
  text "IOREF" at 250.52,166.37 h0.7
  text "A0" at 273.736,164.694 h0.7
  text "A1" at 276.286,164.694 h0.7
  text "A2" at 278.836,164.694 h0.7
  text "A3" at 281.386,164.694 h0.7
  text "A4" at 283.936,164.694 h0.7
  text "A5" at 286.487,164.694 h0.7
  text "NRST" at 255.397,164.516 h0.7
  text "3V3" at 258.237,164.516 h0.7
  text "5V" at 260.67,164.516 h0.7
  text "GND" at 263.307,164.516 h0.7
  text "GND" at 265.943,164.516 h0.7
  text "VIN" at 268.58,164.516 h0.7
Bottom Overlay:
  drawing of 537 lines, arcs and shapes, not listed
  text "ST-LINK DEBUG" at 277.622,215.646 h0.7
  text "5V_ARD" at 270.328,211.006 h0.7 r330
  text "5V_VBAT" at 265.727,210.694 h0.7 r330
  text "5V_USB_FS" at 269.377,210.144 h0.7 r330
  text "5V_ST_LINK" at 274.295,210.126 h0.7 r330
  text "5V_USB_CHARGER" at 267.157,208.204 h0.7 r330
  text "IDD" at 267.767,200.457 h0.7
  text "www.st.com/stm32app-discovery" at 264.262,198.349 h1
  text "TAG connector" at 293.116,187.706 h0.5 r270
  text "SWD Interface" at 293.878,187.198 h0.7 r270
  text "RESET" at 273.025,185.572 h0.7 r270
  text "STLINK" at 273.964,185.547 h0.7 r270
  text "RX" at 282.397,183.439 h0.7
  text "TX" at 284.836,183.413 h0.7
  text "GND" at 241.3,181.356 h0.7
  text "STLINK" at 284.658,179.553 h0.7
  text "UART" at 284.582,178.587 h0.7
  text "GND" at 274.828,178.054 h0.7
  text "J" at 219.964,158.928 h1.52
  text "C" at 219.761,158.699 h1.2
Mecha Dim:
  lines w0: 305.608,163.89 305.942,162.89 ; 305.609,182.89 305.943,183.89 ; 305.688,162.89 306.196,162.89 ; 305.689,183.89 306.197,183.89 ; 305.942,169.985 305.942,162.89 ; 305.942,176.796 305.943,183.89 ; 306.275,163.89 305.942,162.89 ; 306.276,182.89 305.943,183.89
  lines w0.1: 203.352,216.64 309.321,216.64 ; 206.045,161.64 309.753,161.64 ; 210.16,158.14 216.027,158.14 ; 212.318,155.879 212.318,160.552 ; 212.319,217.955 212.319,229.895 ; 215.819,154.94 215.819,226.416 ; 290.043,183.89 306.654,183.89 ; 290.119,162.89 306.807,162.89 ; 293.141,159.969 293.141,186.334 ; 298.819,156.591 298.819,226.847 ; 299.187,158.14 312.471,158.166 ; 299.872,220.14 312.674,220.14 ; 302.319,217.653 302.319,229.641
  lines w0.254: 212.319,227.886 212.319,228.394 ; 213.843,227.632 212.319,228.14 ; 213.843,228.648 212.319,228.14 ; 215.819,223.186 215.819,223.694 ; 217.343,222.932 215.819,223.44 ; 217.343,223.948 215.819,223.44 ; 252.215,223.44 215.819,223.44 ; 252.215,228.14 212.319,228.14 ; 262.422,223.44 298.819,223.44 ; 262.422,228.14 302.319,228.14 ; 297.295,222.932 298.819,223.44 ; 297.295,223.948 298.819,223.44 ; 298.819,223.186 298.819,223.694 ; 300.795,227.632 302.319,228.14 ; 300.795,228.648 302.319,228.14 ; 302.319,227.886 302.319,228.394 ; 307.939,163.164 308.447,161.64 ; 307.939,215.116 308.447,216.64 ; 308.193,161.64 308.701,161.64 ; 308.193,216.64 308.701,216.64 ; 308.447,184.037 308.447,161.64 ; 308.447,194.244 308.447,216.64 ; 308.955,163.164 308.447,161.64 ; 308.955,215.116 308.447,216.64 ; 311.027,159.664 311.535,158.14 ; 311.027,218.616 311.535,220.14 ; 311.281,158.14 311.789,158.14 ; 311.281,220.14 311.789,220.14 ; 311.535,184.037 311.535,158.14 ; 311.535,194.244 311.535,220.14 ; 312.043,159.664 311.535,158.14 ; 312.043,218.616 311.535,220.14
  text "90 (mm)" at 252.469,227.226 h1.52
  text "83 (mm)" at 252.469,222.526 h1.52
  text "55 (mm)" at 309.362,184.291 h1.52 r90
  text "62 (mm)" at 312.449,184.291 h1.52 r90
  text "MEMS Microphones" at 305.283,170.332 h0.5 r90
  text "21 (mm)" at 306.594,170.239 h1 r90
Mechanical 13:
  circle w0.254: c298.819,216.64 r3.25
  circle w0.254: c215.819,216.64 r3.25
  circle w0.254: c215.819,161.64 r3.25
  circle w0.254: c298.819,161.64 r3.25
